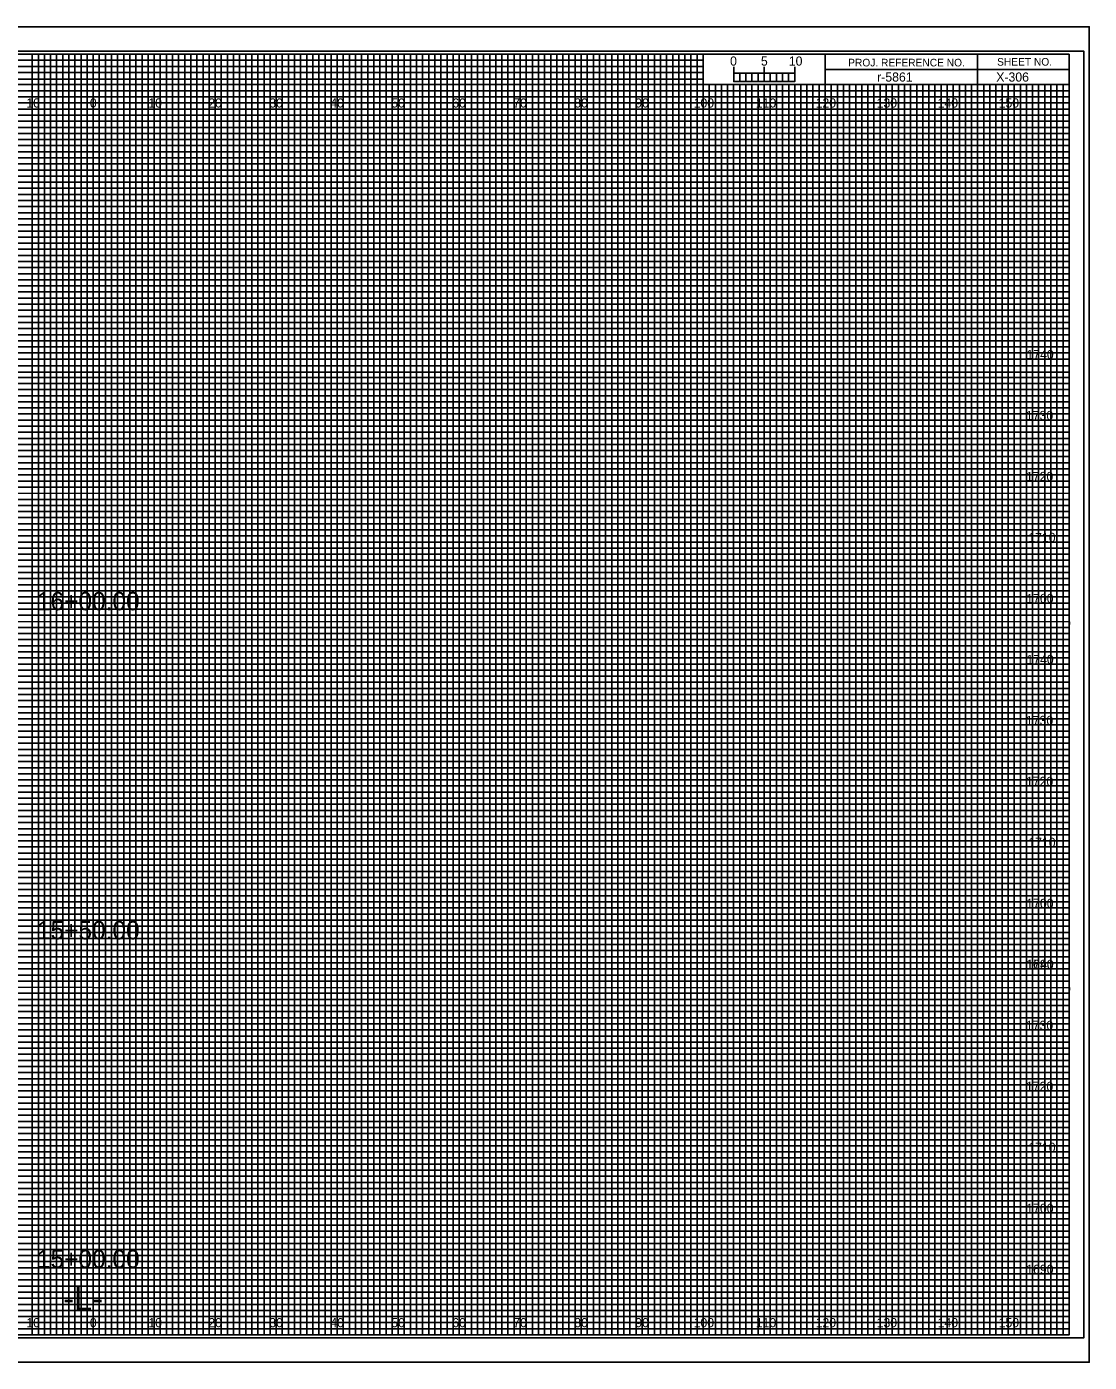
# Model space of a CAD drawing. Extents: x -15 to 323, y -5 to 6170.
# Drawn here: x 149.1 to 323.3, y 435.5 to 654.5 of the extents above; entities that cross this region are included whole.
import ezdxf

# ---------------------------------------------------------------- set-up
doc = ezdxf.new("R2010")
doc.units = 0
for name, color, linetype in [('Prop XS Alignment Label', 7, 'Continuous'), ('Prop XS Bar Scale Labels', 7, 'Continuous'), ('Prop XS DDE', 7, 'Continuous'), ('Prop XS DDE Earthwork Shape', 7, 'Continuous'), ('Prop XS DDE Slope Text', 7, 'Continuous'), ('Prop XS DDE Text', 7, 'Continuous'), ('Prop XS Earthwork Shape', 7, 'Continuous'), ('Prop XS Noise Wall', 7, 'Continuous'), ('Prop XS Project Number', 7, 'Continuous'), ('Prop XS Retaining Wall', 7, 'Continuous'), ('Prop XS Station Labels', 7, 'Continuous'), ('Prop XS Temporary Shoring', 7, 'Continuous'), ('Scratch_Level_3', 7, 'Continuous'), ('Scratch_Level_7', 7, 'Continuous'), ('Scratch_Level_8', 7, 'Continuous'), ('Sheet Cross Section Grid Minor 1 CELL', 7, 'Continuous')]:
    doc.layers.add(name, color=color, linetype=linetype)

msp = doc.modelspace()

# ---------------------------------------------------------------- linework, layer by layer
at = {"layer": 'Prop XS Alignment Label'}
for p, q in [((265, 645.49), (265, 647.9)), ((265, 646.9), (265, 647.9)), ((270, 645.49), (270, 647.9)), ((275, 645.49), (275, 647.9)), ((275, 646.9), (275, 647.9))]:
    msp.add_line(p, q, dxfattribs=at)
for points in [[(275, 646.9), (265, 646.9), (265, 645.49), (275, 645.49)], [(265, 646.9), (266, 646.9), (266, 645.49), (265, 645.49)], [(267, 646.9), (268, 646.9), (268, 645.49), (267, 645.49)], [(269, 646.9), (270, 646.9), (270, 645.49), (269, 645.49)], [(271, 646.9), (272, 646.9), (272, 645.49), (271, 645.49)], [(273, 646.9), (274, 646.9), (274, 645.49), (273, 645.49)]]:
    msp.add_lwpolyline(points, close=True, dxfattribs=at)
at = {"layer": 'Prop XS DDE'}
msp.add_lwpolyline([(-13.4, 435.5), (323.3, 435.5), (323.3, 654.5), (-13.4, 654.5)], close=True, dxfattribs=at)
at = {"layer": 'Prop XS DDE Slope Text'}
msp.add_lwpolyline([(-10.8, 439.5), (322.4, 439.5), (322.4, 650.5), (-10.8, 650.5)], close=True, dxfattribs=at)
at = {"layer": 'Prop XS DDE Text'}
for p, q in [((150, 440), (150, 650)), ((160, 440), (160, 650)), ((170, 440), (170, 650)), ((180, 440), (180, 650)), ((190, 440), (190, 650)), ((200, 440), (200, 650)), ((210, 440), (210, 650)), ((220, 440), (220, 650)), ((230, 440), (230, 650)), ((240, 440), (240, 650)), ((250, 440), (250, 650)), ((260, 440), (260, 644.69)), ((270, 440), (270, 644.69)), ((280, 440), (280, 644.69)), ((290, 440), (290, 644.69)), ((300, 440), (300, 644.69)), ((310, 440), (310, 644.69)), ((0, 640), (320, 640)), ((0, 630), (320, 630)), ((0, 620), (320, 620)), ((0, 610), (320, 610)), ((0, 600), (320, 600)), ((0, 590), (320, 590)), ((0, 580), (320, 580)), ((0, 570), (320, 570)), ((0, 560), (320, 560)), ((0, 550), (320, 550)), ((0, 540), (320, 540)), ((0, 530), (320, 530)), ((0, 520), (320, 520)), ((0, 510), (320, 510)), ((0, 500), (320, 500)), ((0, 490), (320, 490)), ((0, 480), (320, 480)), ((0, 470), (320, 470)), ((0, 460), (320, 460)), ((0, 450), (320, 450))]:
    msp.add_line(p, q, dxfattribs=at)
at = {"layer": 'Prop XS Earthwork Shape'}
for p, q in [((150, 650), (140, 650)), ((150, 440), (150, 650)), ((170, 650), (160, 650)), ((160, 650), (160, 440)), ((170, 440), (170, 650)), ((190, 650), (180, 650)), ((180, 650), (180, 440)), ((190, 440), (190, 650)), ((210, 650), (200, 650)), ((200, 650), (200, 440)), ((210, 440), (210, 650)), ((230, 650), (220, 650)), ((220, 650), (220, 440)), ((230, 440), (230, 650)), ((250, 650), (240, 650)), ((240, 650), (240, 440)), ((250, 440), (250, 650)), ((260, 650), (260, 440)), ((270, 440), (270, 645)), ((290, 645), (280, 645)), ((280, 645), (280, 440)), ((290, 440), (290, 645)), ((310, 645), (300, 645)), ((300, 645), (300, 440)), ((310, 440), (310, 645)), ((160, 440), (150, 440)), ((180, 440), (170, 440)), ((200, 440), (190, 440)), ((220, 440), (210, 440)), ((240, 440), (230, 440)), ((260, 440), (250, 440)), ((280, 440), (270, 440)), ((300, 440), (290, 440)), ((320, 440), (310, 440)), ((320, 440), (320, 440))]:
    msp.add_line(p, q, dxfattribs=at)
for points in [[(0, 640), (320, 640), (320, 630), (0, 630)], [(0, 620), (320, 620), (320, 610), (0, 610)], [(0, 600), (320, 600), (320, 590), (0, 590)], [(0, 580), (320, 580), (320, 570), (0, 570)], [(0, 560), (320, 560), (320, 550), (0, 550)], [(0, 540), (320, 540), (320, 530), (0, 530)], [(0, 520), (320, 520), (320, 510), (0, 510)], [(0, 500), (320, 500), (320, 490), (0, 490)], [(0, 480), (320, 480), (320, 470), (0, 470)], [(0, 460), (320, 460), (320, 450), (0, 450)]]:
    msp.add_lwpolyline(points, dxfattribs=at)
at = {"layer": 'Prop XS Noise Wall'}
for p, q in [((305, 650), (305, 645)), ((305, 645), (305, 650)), ((280, 647.5), (280, 645)), ((320, 647.49), (280, 647.49)), ((280, 645), (320, 645))]:
    msp.add_line(p, q, dxfattribs=at)
for points in [[(320, 650), (0, 650), (0, 440), (320, 440)], [(280, 650), (260, 650), (260, 645.03), (280, 645.03)], [(320, 650), (280, 650), (280, 645), (320, 645)]]:
    msp.add_lwpolyline(points, close=True, dxfattribs=at)
at = {"layer": 'Prop XS Retaining Wall'}
for p, q in [((267, 645), (266.01, 645)), ((266.01, 645), (266.01, 440)), ((267, 440), (267, 645)), ((269, 645), (268, 645)), ((268, 645), (268, 440)), ((269, 440), (269, 645)), ((266.01, 440), (265, 440)), ((268, 440), (267, 440))]:
    msp.add_line(p, q, dxfattribs=at)
for points in [[(150, 440), (151, 440), (151, 650), (152, 650), (152, 440)], [(152, 440), (153, 440), (153, 650), (154, 650), (154, 440)], [(155, 440), (156, 440), (156, 650), (157, 650), (157, 440)], [(157, 440), (158, 440), (158, 650), (159, 650), (159, 440)], [(160, 440), (161, 440), (161, 650), (162, 650), (162, 440)], [(162, 440), (163, 440), (163, 650), (164, 650), (164, 440)], [(165, 440), (166, 440), (166, 650), (167, 650), (167, 440)], [(167, 440), (168, 440), (168, 650), (169, 650), (169, 440)], [(170, 440), (171, 440), (171, 650), (172, 650), (172, 440)], [(172, 440), (173, 440), (173, 650), (174, 650), (174, 440)], [(175, 440), (176, 440), (176, 650), (177, 650), (177, 440)], [(177, 440), (178, 440), (178, 650), (179, 650), (179, 440)], [(180, 440), (181, 440), (181, 650), (182, 650), (182, 440)], [(182, 440), (183, 440), (183, 650), (184, 650), (184, 440)], [(185, 440), (186, 440), (186, 650), (187, 650), (187, 440)], [(187, 440), (188, 440), (188, 650), (189, 650), (189, 440)], [(190, 440), (191, 440), (191, 650), (192, 650), (192, 440)], [(192, 440), (193, 440), (193, 650), (194, 650), (194, 440)], [(195, 440), (196, 440), (196, 650), (197, 650), (197, 440)], [(197, 440), (198, 440), (198, 650), (199, 650), (199, 440)], [(200, 440), (201, 440), (201, 650), (202, 650), (202, 440)], [(202, 440), (203, 440), (203, 650), (204, 650), (204, 440)], [(205, 440), (206, 440), (206, 650), (207, 650), (207, 440)], [(207, 440), (208, 440), (208, 650), (209, 650), (209, 440)], [(210, 440), (211, 440), (211, 650), (212, 650), (212, 440)], [(212, 440), (213, 440), (213, 650), (214, 650), (214, 440)], [(215, 440), (216, 440), (216, 650), (217, 650), (217, 440)], [(217, 440), (218, 440), (218, 650), (219, 650), (219, 440)], [(220, 440), (221, 440), (221, 650), (222, 650), (222, 440)], [(222, 440), (223, 440), (223, 650), (224, 650), (224, 440)], [(225, 440), (226, 440), (226, 650), (227, 650), (227, 440)], [(227, 440), (228, 440), (228, 650), (229, 650), (229, 440)], [(230, 440), (231, 440), (231, 650), (232, 650), (232, 440)], [(232, 440), (233, 440), (233, 650), (234, 650), (234, 440)], [(235, 440), (236, 440), (236, 650), (237, 650), (237, 440)], [(237, 440), (238, 440), (238, 650), (239, 650), (239, 440)], [(240, 440), (241, 440), (241, 650), (242, 650), (242, 440)], [(242, 440), (243, 440), (243, 650), (244, 650), (244, 440)], [(245, 440), (246, 440), (246, 650), (247, 650), (247, 440)], [(247, 440), (248, 440), (248, 650), (249, 650), (249, 440)], [(250, 440), (251, 440), (251, 650), (252, 650), (252, 440)], [(252, 440), (253, 440), (253, 650), (254, 650), (254, 440)], [(255, 440), (256, 440), (256, 650), (257, 650), (257, 440)], [(257, 440), (258, 440), (258, 650), (259, 650), (259, 440)], [(260, 440), (261, 440), (261, 645), (262.02, 645), (262.02, 440)], [(262, 440), (263, 440), (263, 645), (263.99, 645), (263.99, 440)], [(270, 440), (270.98, 440), (270.98, 645), (272, 645), (272, 440)], [(272, 440), (273, 440), (273, 645), (274.05, 645), (274.05, 440)], [(275, 440), (276, 440), (276, 645), (277, 645), (277, 440)], [(277, 440), (278, 440), (278, 645), (279, 645), (279, 440)], [(280, 440), (281, 440), (281, 645), (282, 645), (282, 440)], [(282, 440), (283, 440), (283, 645), (284, 645), (284, 440)], [(285, 440), (286, 440), (286, 645), (287, 645), (287, 440)], [(287, 440), (288, 440), (288, 645), (289, 645), (289, 440)], [(290, 440), (291, 440), (291, 645), (292, 645), (292, 440)], [(292, 440), (293, 440), (293, 645), (294, 645), (294, 440)], [(295, 440), (296, 440), (296, 645), (297, 645), (297, 440)], [(297, 440), (298, 440), (298, 645), (299, 645), (299, 440)], [(300, 440), (301, 440), (301, 645), (302, 645), (302, 440)], [(302, 440), (303, 440), (303, 645), (304, 645), (304, 440)], [(305, 440), (306, 440), (306, 645), (307, 645), (307, 440)], [(307, 440), (308, 440), (308, 645), (309, 645), (309, 440)], [(310, 440), (311, 440), (311, 645), (312, 645), (312, 440)], [(312, 440), (313, 440), (313, 645), (314, 645), (314, 440)], [(315, 440), (316, 440), (316, 645), (317, 645), (317, 440)], [(317, 440), (318, 440), (318, 645), (319, 645), (319, 440)]]:
    msp.add_lwpolyline(points, dxfattribs=at)
at = {"layer": 'Prop XS Station Labels'}
for points in [[(145, 440), (155, 440), (155, 650), (165, 650), (165, 440), (175, 440), (175, 650), (185, 650), (185, 440), (195, 440), (195, 650), (205, 650), (205, 440), (215, 440), (215, 650), (225, 650), (225, 440), (235, 440), (235, 650), (245, 650), (245, 440), (255, 440), (255, 650), (259.93, 650), (260, 650), (260, 645), (264.99, 645), (264.99, 440), (275, 440), (275, 645), (285, 645), (285, 440), (295, 440), (295, 645), (305, 645), (305, 440), (315, 440), (315, 645)], [(0, 645), (275, 645)], [(0, 625), (320, 625), (320, 635), (0, 635)], [(0, 605), (320, 605), (320, 615), (0, 615)], [(0, 585), (320, 585), (320, 595), (0, 595)], [(0, 565), (320, 565), (320, 575), (0, 575)], [(0, 545), (320, 545), (320, 555), (0, 555)], [(0, 525), (320, 525), (320, 535), (0, 535)], [(0, 505), (320, 505), (320, 515), (0, 515)], [(0, 485), (320, 485), (320, 495), (0, 495)], [(0, 465), (320, 465), (320, 475), (0, 475)], [(0, 445), (320, 445), (320, 455), (0, 455)]]:
    msp.add_lwpolyline(points, dxfattribs=at)
at = {"layer": 'Scratch_Level_7'}
for p, q in [((323.3, 654.5), (-13.4, 654.5)), ((-13.4, 435.5), (323.3, 435.5))]:
    msp.add_line(p, q, dxfattribs=at)
at = {"layer": 'Sheet Cross Section Grid Minor 1 CELL'}
for p, q in [((0, 649), (260, 649)), ((260, 649), (260, 647.98)), ((260, 647.98), (0, 647.98)), ((0, 647), (260, 647)), ((260, 647), (260, 645.89)), ((260, 645.89), (0, 645.89)), ((0, 644), (320, 644))]:
    msp.add_line(p, q, dxfattribs=at)
for points in [[(0, 643), (270, 643), (320, 643), (320, 642), (0, 642)], [(0, 641), (320, 641), (320, 639), (0, 639)], [(0, 638), (320, 638), (320, 637), (0, 636.98)], [(0, 636), (320, 636), (320, 634), (0, 634)], [(0, 633), (320, 633), (320, 632), (0, 632)], [(0, 631), (320, 631), (320, 629), (0, 629)], [(0, 628), (320, 628), (320, 627), (0, 627)], [(0, 626), (320, 626), (320, 624), (0, 624)], [(0, 623), (320, 623), (320, 622), (0, 622)], [(0, 621), (320, 621), (320, 619), (0, 619)], [(0, 618), (320, 618), (320, 617), (0, 617)], [(0, 616), (320, 616), (320, 613.95), (320, 613), (320, 612), (0, 612)], [(0, 614), (320, 614), (320, 613), (0, 613)], [(0, 611), (320, 611), (320, 609), (0, 609.03)], [(0, 609.03), (320, 609), (320, 608), (0, 608)], [(0, 607), (320, 607), (320, 606), (0, 606)], [(0, 604), (320, 604), (320, 603), (0, 603)], [(0, 602), (320, 602), (320, 601), (0, 601)], [(-0.07, 598.89), (320, 598.89), (320, 597.88), (-0.07, 597.88)], [(0, 597), (320, 597), (320, 596), (0, 596)], [(0, 594), (320, 594), (320, 593), (0, 593)], [(0, 592), (320, 592), (320, 591), (0, 591)], [(0, 589), (320, 589), (320, 588), (0, 588)], [(0, 587), (320, 587), (320, 586), (0, 586)], [(0, 584), (320, 584), (320, 583), (0, 583)], [(0, 582), (320, 582), (320, 581), (0, 581)], [(0, 579), (320, 579), (319.99, 577.98), (0, 578)], [(0, 577), (320, 577), (320, 576), (0, 576)], [(0, 574), (320, 574), (320, 573), (0, 573)], [(0, 572), (320, 572), (320, 571), (0, 571)], [(0, 569), (320, 569), (320, 568), (0, 568)], [(0, 567), (320, 567), (320, 566), (0, 566)], [(0, 564), (320, 564), (320, 563), (0, 563)], [(0, 562), (320, 562), (320, 561), (0, 561)], [(0, 559), (320, 559), (320, 558), (0, 558)], [(0, 556.99), (320.07, 556.91), (320, 556), (0, 556)], [(0, 554), (320, 554), (320, 553), (0, 553)], [(0, 552), (320, 552), (320, 551), (0, 551)], [(0, 549), (320, 549), (320, 548), (0, 548)], [(0, 547), (320, 547), (320, 546), (0, 546)], [(0, 544), (320, 544), (320, 543), (0, 543)], [(0, 542), (320, 542), (320, 541), (0, 541)], [(0, 539), (320, 539), (320, 538), (0, 538)], [(0, 537), (320, 537), (320, 536), (0, 536)], [(0, 534), (320, 534), (320, 533), (0, 533)], [(0, 532), (320, 532), (320, 531), (0, 531)], [(0, 529), (320, 529), (320, 528), (0, 528)], [(0, 527), (320, 527), (320, 526), (0, 526)], [(0, 524), (320, 524), (320, 523), (0, 523)], [(0, 522), (320, 522), (320, 521), (0, 521)], [(0, 519), (320, 519), (319.99, 517.98), (0, 518)], [(0, 517), (320, 517), (320, 516), (0, 516)], [(0, 514), (320, 514), (320, 513), (0, 513)], [(0, 512), (320, 512), (320, 511), (0, 511)], [(0, 509), (320, 509), (320, 508), (0, 508)], [(0, 507), (320, 507), (320, 506), (0, 506)], [(0, 504), (320, 504), (320, 503), (0, 503)], [(0, 502), (320, 502), (320, 501), (0, 501)], [(0, 499), (320, 499), (320, 498), (0, 498)], [(0, 496.99), (320.07, 496.91), (320, 496), (0, 496)], [(0, 494), (320, 494), (320, 493), (0, 493)], [(0, 492), (320, 492), (320, 491), (0, 491)], [(0, 489), (320, 489), (320, 488), (0, 488)], [(0, 487), (320, 487), (320, 486), (0, 486)], [(0, 484), (320, 484), (320, 483), (0, 483)], [(0, 482), (320, 482), (320, 481), (0, 481)], [(0, 479), (320, 479), (320, 478), (0, 478)], [(0, 477), (320, 477), (320, 476), (0, 476)], [(0, 474), (320, 474), (320, 473), (0, 473)], [(0, 472), (320, 472), (320, 471), (0, 471)], [(0, 469), (320, 469), (320, 468), (0, 468)], [(0, 467), (320, 467), (320, 466), (0, 466)], [(0, 464), (320, 464), (320, 463), (0, 463)], [(0, 462), (320, 462), (320, 461), (0, 461)], [(0, 459), (320, 459), (320, 458), (0, 458)], [(0, 457), (320, 457), (320, 456), (0, 456)], [(0, 454), (320, 454), (320, 453), (0, 453)], [(0, 452), (320, 452), (320, 451), (0, 451)], [(0, 449), (320, 449), (320, 448), (0, 448)], [(0, 447), (320, 447), (320, 446), (0, 446)], [(0, 444), (320, 444), (320, 443), (0, 443)], [(0, 442), (320, 442), (320, 441), (0, 441)]]:
    msp.add_lwpolyline(points, dxfattribs=at)

# ---------------------------------------------------------------- texts
at = {"layer": 'Prop XS Alignment Label'}
for s, height, p in [('0', 1.5, (264.41, 648.12)), ('-L-', 4, (155.06, 444))]:
    msp.add_text(s, height=height, dxfattribs=at).set_placement(p)
at = {"layer": 'Prop XS Bar Scale Labels'}
for s, p in [('5', (269.47, 648.12)), ('10', (274.04, 648.12))]:
    msp.add_text(s, height=1.5, dxfattribs=at).set_placement(p)
at = {"layer": 'Prop XS DDE Earthwork Shape'}
msp.add_text('X-306', height=1.5, dxfattribs=at).set_placement((308.05, 645.5))
at = {"layer": 'Prop XS Noise Wall'}
for s, p in [('PROJ. REFERENCE NO.', (283.77, 647.99)), ('SHEET NO.', (308.19, 648.12))]:
    msp.add_text(s, height=1.25, dxfattribs=at).set_placement(p)
at = {"layer": 'Prop XS Project Number'}
msp.add_text('r-5861', height=1.5, dxfattribs=at).set_placement((288.53, 645.5))
at = {"layer": 'Prop XS Temporary Shoring'}
for s, p in [('16+00.00', (150.77, 558.81)), ('15+50.00', (150.77, 504.85)), ('15+00.00', (150.77, 450.94))]:
    msp.add_text(s, height=3, dxfattribs=at).set_placement(p)
at = {"layer": 'Scratch_Level_3'}
for s, p in [('1740', (313, 600)), ('1730', (312.92, 590)), ('1720', (312.93, 580)), ('1710', (313.31, 570)), ('1700', (312.98, 560)), ('1740', (313, 550)), ('1730', (312.92, 540)), ('1720', (312.93, 530)), ('1710', (313.31, 520)), ('1700', (312.98, 510)), ('1690', (312.97, 500)), ('1740', (313, 500)), ('1730', (312.92, 490)), ('1720', (312.93, 480)), ('1710', (313.31, 470)), ('1700', (312.98, 460)), ('1690', (312.97, 450))]:
    msp.add_text(s, height=1.5, dxfattribs=at).set_placement(p)
at = {"layer": 'Scratch_Level_8'}
for s, p in [('10', (149.04, 641.25)), ('0', (159.45, 641.25)), ('0', (159.45, 641.25)), ('10', (169.04, 641.25)), ('20', (178.86, 641.25)), ('30', (188.86, 641.25)), ('40', (198.86, 641.25)), ('50', (208.86, 641.25)), ('60', (218.86, 641.25)), ('70', (228.86, 641.25)), ('80', (238.86, 641.25)), ('90', (248.86, 641.25)), ('100', (258.44, 641.25)), ('110', (268.62, 641.25)), ('120', (278.44, 641.25)), ('130', (288.44, 641.25)), ('140', (298.44, 641.25)), ('150', (308.44, 641.25)), ('10', (149.04, 441.25)), ('0', (159.45, 441.25)), ('0', (159.45, 441.25)), ('10', (169.04, 441.25)), ('20', (178.86, 441.25)), ('30', (188.86, 441.25)), ('40', (198.86, 441.25)), ('50', (208.86, 441.25)), ('60', (218.86, 441.25)), ('70', (228.86, 441.25)), ('80', (238.86, 441.25)), ('90', (248.86, 441.25)), ('100', (258.44, 441.25)), ('110', (268.62, 441.25)), ('120', (278.44, 441.25)), ('130', (288.44, 441.25)), ('140', (298.44, 441.25)), ('150', (308.44, 441.25))]:
    msp.add_text(s, height=1.5, dxfattribs=at).set_placement(p)

doc.saveas('drawing.dxf')
